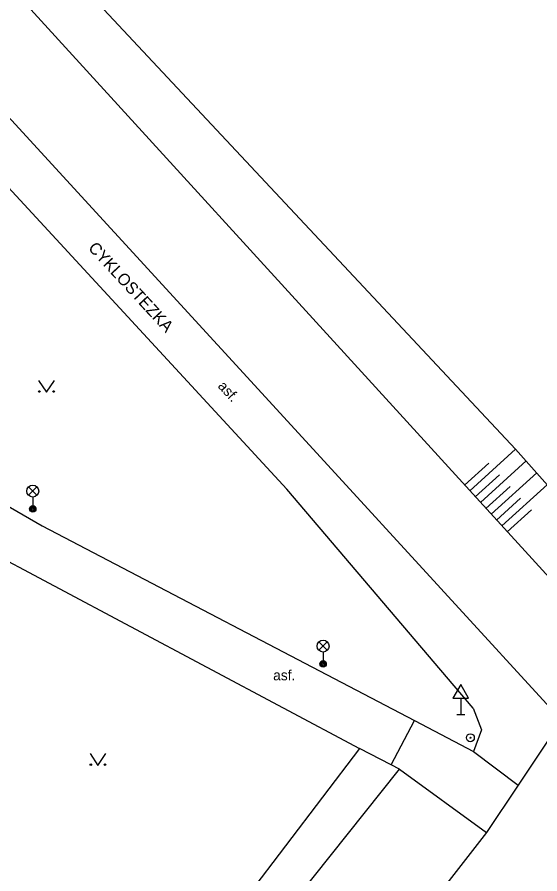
# Model space of a CAD drawing. Extents: x -598932 to -598196, y -1162207 to -1161504.
# Drawn here: x -598777.3 to -598744.3, y -1161938.6 to -1161884.4 of the extents above; entities that cross this region are included whole.
import ezdxf

# ---------------------------------------------------------------- set-up
doc = ezdxf.new("R2010")
doc.units = 0
for name, color, linetype in [('Level 25', 7, 'Continuous'), ('Level 33', 7, 'Continuous'), ('Level 34', 7, 'Continuous'), ('Level 36', 7, 'Continuous'), ('specificka linie pasportu komunikaci', 7, 'Continuous'), ('TM - chodniky - VP', 7, 'Continuous'), ('TM - hladina vodniho toku_ bazenu_ nadrze', 7, 'Continuous'), ('TM - horni hrana svahu', 7, 'Continuous'), ('TM - popis objektu', 7, 'Continuous'), ('TM - popis povrchu', 7, 'Continuous'), ('TM - rozhrani ploch obecne - VP', 7, 'Continuous'), ('TM - srafovani', 7, 'Continuous')]:
    doc.layers.add(name, color=color, linetype=linetype)

msp = doc.modelspace()

# ---------------------------------------------------------------- linework, layer by layer
at = {"layer": 'Level 25'}
for radius in [0.25, 0.0303]:
    msp.add_circle((-598748.68, -1161929.98), radius, dxfattribs=at)
at = {"layer": 'Level 33'}
for p, q in [((-598776.615, -1161914.65), (-598776.085, -1161914.12)), ((-598776.615, -1161914.12), (-598776.085, -1161914.65)), ((-598776.35, -1161914.76), (-598776.35, -1161915.51)), ((-598758.255, -1161924.45), (-598757.725, -1161923.92)), ((-598758.255, -1161923.92), (-598757.725, -1161924.45)), ((-598757.99, -1161924.56), (-598757.99, -1161925.31))]:
    msp.add_line(p, q, dxfattribs=at)
for centre, radius in [((-598776.35, -1161914.385), 0.375), ((-598776.35, -1161915.51), 0.2), ((-598776.35, -1161915.51), 0.145), ((-598776.35, -1161915.51), 0.0876), ((-598757.99, -1161924.185), 0.375), ((-598757.99, -1161925.31), 0.2), ((-598757.99, -1161925.31), 0.145), ((-598757.99, -1161925.31), 0.0876)]:
    msp.add_circle(centre, radius, dxfattribs=at)
at = {"layer": 'Level 34'}
for p, q in [((-598749.29, -1161927.482), (-598749.29, -1161928.5)), ((-598749.54, -1161928.5), (-598749.04, -1161928.5))]:
    msp.add_line(p, q, dxfattribs=at)
msp.add_lwpolyline([(-598749.79, -1161927.482), (-598748.79, -1161927.482), (-598749.29, -1161926.616)], close=True, dxfattribs=at)
at = {"layer": 'Level 36'}
for points in [[(-598775.98, -1161907.39), (-598775.48, -1161908.14), (-598774.98, -1161907.39)], [(-598772.73, -1161930.98), (-598772.23, -1161931.73), (-598771.73, -1161930.98)]]:
    msp.add_lwpolyline(points, dxfattribs=at)
for centre in [(-598775.93, -1161908.09), (-598775.031, -1161908.09), (-598772.68, -1161931.68), (-598771.781, -1161931.68)]:
    msp.add_circle(centre, 0.05, dxfattribs=at)
at = {"layer": 'specificka linie pasportu komunikaci'}
for points in [[(-598753.69, -1161931.69), (-598752.22, -1161928.89)], [(-598748.49, -1161930.84), (-598745.65, -1161932.97)]]:
    msp.add_lwpolyline(points, dxfattribs=at)
at = {"layer": 'TM - chodniky - VP'}
for points in [[(-598803.26, -1161864), (-598777.69, -1161890.94), (-598758.15, -1161912.24), (-598742.93, -1161928.84)], [(-598748.5, -1161928.1), (-598760.28, -1161914.27), (-598779.92, -1161893), (-598802.56, -1161869.04)], [(-598818.34, -1161891.95), (-598775.76, -1161916.58), (-598752.22, -1161928.89), (-598748.49, -1161930.84)], [(-598789.55, -1161926.86), (-598789.35, -1161926.65), (-598796.39, -1161919.59), (-598789.49, -1161912.66), (-598755.69, -1161930.65)], [(-598748.5, -1161928.1), (-598747.98, -1161929.47)], [(-598747.98, -1161929.47), (-598748.49, -1161930.84)], [(-598755.69, -1161930.65), (-598767.39, -1161946.04)], [(-598766.15, -1161948.25), (-598753.16, -1161931.96)], [(-598753.16, -1161931.96), (-598747.66, -1161935.98)], [(-598747.66, -1161935.98), (-598760.48, -1161952.44)]]:
    msp.add_lwpolyline(points, dxfattribs=at)
at = {"layer": 'TM - hladina vodniho toku_ bazenu_ nadrze'}
msp.add_lwpolyline([(-598818.85, -1161831.09), (-598788.93, -1161865.71), (-598745.82, -1161911.74), (-598735.06, -1161923.85)], dxfattribs=at)
at = {"layer": 'TM - horni hrana svahu'}
msp.add_lwpolyline([(-598737.74, -1161926.39), (-598791.69, -1161867.26), (-598813.1, -1161843.8), (-598846.83, -1161807.87), (-598870.15, -1161785.99), (-598909.01, -1161754.64), (-598931.6, -1161739.49), (-598932.017, -1161739.209)], dxfattribs=at)
at = {"layer": 'TM - rozhrani ploch obecne - VP'}
for points in [[(-598736.15, -1161932.08), (-598737.9, -1161932.17), (-598739.9, -1161931.74), (-598743.12, -1161929.18), (-598745.65, -1161932.97), (-598747.66, -1161935.98)], [(-598753.16, -1161931.96), (-598753.69, -1161931.69), (-598755.69, -1161930.65)]]:
    msp.add_lwpolyline(points, dxfattribs=at)
at = {"layer": 'TM - srafovani'}
for points in [[(-598745.82, -1161911.74), (-598748.71, -1161914.37)], [(-598745.15, -1161912.48), (-598748.03, -1161915.11)], [(-598747.52, -1161912.61), (-598749.05, -1161914)], [(-598746.84, -1161913.35), (-598748.37, -1161914.74)], [(-598744.47, -1161913.22), (-598747.36, -1161915.85)], [(-598746.17, -1161914.09), (-598747.7, -1161915.48)], [(-598743.8, -1161913.96), (-598746.69, -1161916.59)], [(-598745.5, -1161914.83), (-598747.02, -1161916.22)], [(-598744.82, -1161915.57), (-598746.35, -1161916.96)]]:
    msp.add_lwpolyline(points, dxfattribs=at)

# ---------------------------------------------------------------- texts
at = {"layer": 'TM - popis objektu'}
msp.add_text('CYKLOSTEZKA', height=0.75, rotation=312.72, dxfattribs=at).set_placement((-598772.89, -1161899.05))
at = {"layer": 'TM - popis povrchu'}
msp.add_text('asf.', height=0.65, rotation=312.72, dxfattribs=at).set_placement((-598764.69, -1161907.78))
msp.add_text('asf.', height=0.65, dxfattribs=at).set_placement((-598761.15, -1161926.35))

doc.saveas('drawing.dxf')
